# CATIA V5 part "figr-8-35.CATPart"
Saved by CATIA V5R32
Part number: Part1
Bounding box of the stored display mesh (mm): x -75 to 75, y -75 to 75, z 0 to 20
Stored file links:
  D:\PROJECTS\Project 2022\CATIA V5 6R 2022\Resources\Part Files\c08_catia_v5_6r2022_prt\figr-8-35.CATPart
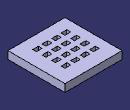
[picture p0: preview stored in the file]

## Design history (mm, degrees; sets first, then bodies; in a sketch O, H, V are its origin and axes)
Body1 (main body)
  Sketch1 on xy-plane, origin (0, 0, 0), H (1, 0, 0), V (0, 1, 0)
    line L1 (-75, 75) -> (75, 75)
    line L2 (75, 75) -> (75, -75)
    line L3 (75, -75) -> (-75, -75)
    line L4 (-75, -75) -> (-75, 75)
    axis line L5 (75, -75) -> (-75, 75)
    length L3 = 150
    length L2 = 150
    horizontal: L1 H, L3 H
    vertical: L2 V, L4 V
    midpoint: O L5
  Pad1: profile Sketch1, direction (0, 0, 1), length 20
  Sketch2 on face of Pad1, origin (0, 0, 20), H (1, 0, 0), V (0, 1, 0)
    line L1 (25, 40) -> (40, 40)
    line L2 (40, 40) -> (40, 30)
    line L3 (40, 30) -> (25, 30)
    line L4 (25, 30) -> (25, 40)
    reference projected line E1 (75, -75) -> (75, 75) from edge [face of Pad1 | face of Pad1]
    reference projected line E2 (75, 75) -> (-75, 75) from edge [face of Pad1 | face of Pad1]
    length L3 = 15
    length L4 = 10
    distance L2 E1 = 35
    distance L1 E2 = 35
    horizontal: L1 H, L3 H
    vertical: L2 V, L4 V
  Pocket1: profile Sketch2, direction (0, 0, -1), through (limit type 3)
  RectPattern1: of Pocket1, direction 1 instances 4, spacing -25, along end face of Pad1, direction 2 instances 4, spacing 25, along end face of Pad1 reversed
